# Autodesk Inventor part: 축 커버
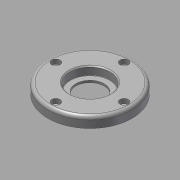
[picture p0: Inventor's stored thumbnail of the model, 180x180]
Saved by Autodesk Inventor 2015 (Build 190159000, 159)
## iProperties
Created: 2015-10
Part Number: 축 커버
Document SubType Name: Modeling
Designer: mdu
Density: 1 g/cm^3
Material: 강철, 연강
Appearance: Steel
Author: mdu
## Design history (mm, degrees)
sketch "스케치1"
  geometry: C1 r 40 at (0, 0) reference; C2 r 26 at (0, 0) reference; 1 further point
  node "참조1"
  node "참조2"
extrude "돌출1" new body sketch "스케치1" distance "d0" = 10; taper "d1" = 0 deg
extrude "돌출2" join sketch "스케치1" distance "d2" = 3; taper "d3" = 0 deg
hole "구멍1" diameter "d6" = 27; stored, may be unused: countersink angle "d10" = 90 deg, drill point angle "d12" = 118 deg; dims "d4" = 10, "d5" = 10, "d7" = 6, "d8" = 38, "d9" = 8, "d11" = 8
sketch "스케치2"
  geometry: C1 r 20 at (0, 0); 1 further point
  constraints: 1 centre point, 1 coincident
  dimensions: "d13" = 40 diameter of C1
extrude "돌출3" cut sketch "스케치2" distance "d14" = 3; taper "d15" = 0 deg
sketch "스케치3"
  geometry: C1 r 1.621 at (0, 32.5) reference; 1 further point
hole "구멍2" sketch "스케치3" at (0, 32.5) diameter "d16" = 4.5; stored, may be unused: countersink angle "d20" = 90 deg, drill point angle "d22" = 118 deg; dims "d17" = 6, "d18" = 8, "d19" = 4.4, "d21" = 8
fillet "모깎기1" dims "d26" = 3, "d27" = 0.3
chamfer "모따기1" distance "d28" = 1; stored, may be unused: second distance "d29" = 2, angle "d30" = 45 deg
node "솔리드1"
pattern_circular "원형 패턴1" dims angle "d24" = 360 deg
node "참조3"
